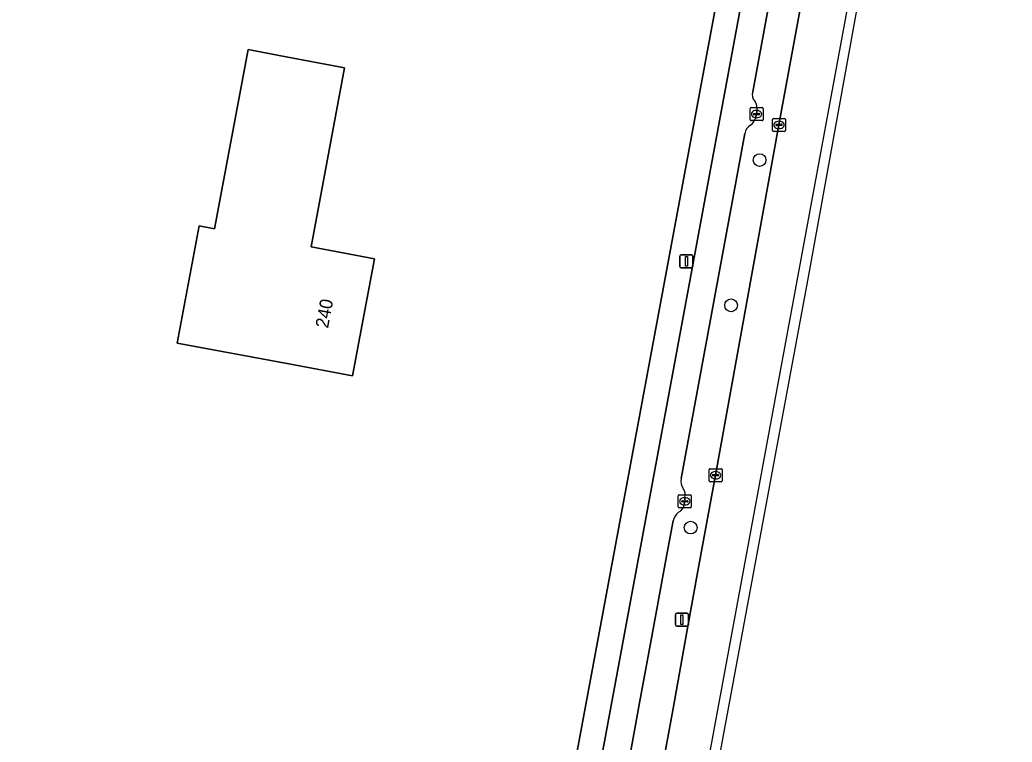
# Model space of a CAD drawing. Extents: x 161258 to 161838, y 380833 to 381727.
# Drawn here: x 161697.6 to 161774.1, y 381168.8 to 381224.5 of the extents above; entities that cross this region are included whole.
import ezdxf

# ---------------------------------------------------------------- set-up
doc = ezdxf.new("R2010")
doc.units = 0
for name, color, linetype in [('IMGEO_Berm_groen', 7, 'Continuous'), ('IMGEO_Boom', 7, 'Continuous'), ('IMGEO_Erf', 7, 'Continuous'), ('IMGEO_Fietspad_open', 7, 'Continuous'), ('IMGEO_Kolk', 7, 'Continuous'), ('IMGEO_Lichtmast', 7, 'Continuous'), ('IMGEO_OVBaan_gesloten', 7, 'Continuous'), ('IMGEO_Pand', 7, 'Continuous'), ('IMGEO_Pand_nummerreeks', 7, 'Continuous'), ('IMGEO_Rijbaan_regionaal_gesloten', 7, 'Continuous'), ('IMGEO_Voetpad_open', 7, 'Continuous')]:
    doc.layers.add(name, color=color, linetype=linetype)

msp = doc.modelspace()

# ---------------------------------------------------------------- linework, layer by layer
at = {"layer": 'IMGEO_Berm_groen'}
for points in [[(161749.906, 381182.432), (161751.199, 381189.4), (161756.087, 381216.391), (161759.764, 381236.501), (161759.812, 381236.731), (161757.806, 381237.074)], [(161756.973, 381234.746), (161754.062, 381218.948)], [(161754.387, 381217.443), (161754.355, 381217.217), (161754.307, 381217.001)], [(161753.462, 381215.738), (161748.553, 381189.132)], [(161748.843, 381187.633), (161748.825, 381187.388), (161748.776, 381187.177)], [(161747.932, 381185.874), (161747.38, 381182.889), (161746.436, 381177.828), (161745.35, 381171.862), (161744.465, 381167.019), (161743.243, 381160.292)], [(161738.935, 381137.075), (161736.688, 381124.974), (161739.276, 381124.46), (161741.999, 381139.338), (161745.882, 381160.426), (161747.045, 381166.542), (161747.93, 381171.425), (161748.988, 381177.338), (161749.906, 381182.432)]]:
    msp.add_lwpolyline(points, dxfattribs=at)
for centre, radius, start, end in [((161754.846, 381218.728), 0.814, 164.34392, 219.20512), ((161753.481, 381217.645), 0.929, 347.40505, 37.74697), ((161753.289, 381217.212), 1.04, 305.73201, 348.27754), ((161754.335, 381215.601), 0.884, 119.78436, 171.09059), ((161749.527, 381188.92), 0.996, 167.72981, 213.94161), ((161747.981, 381187.844), 0.887, 346.24075, 35.89637), ((161748.064, 381187.196), 0.713, 293.08221, 358.50607), ((161749.008, 381185.67), 1.095, 127.38602, 169.25509)]:
    msp.add_arc(centre, radius, start, end, dxfattribs=at)
at = {"layer": 'IMGEO_Boom'}
for centre in [(161754.592, 381213.675), (161752.398, 381202.487), (161749.281, 381185.361)]:
    msp.add_circle(centre, 0.489, dxfattribs=at)
at = {"layer": 'IMGEO_Erf'}
msp.add_lwpolyline([(161668.77, 381167.385), (161673.77, 381165.793), (161737.053, 381153.773), (161737.441, 381153.699), (161737.997, 381153.598), (161738.112, 381154.157), (161737.938, 381154.198), (161753.579, 381238.309), (161753.673, 381238.82), (161753.349, 381239.081), (161753.133, 381238.804), (161751.742, 381240.033), (161751.586, 381239.216), (161750.481, 381239.459), (161750.713, 381240.543), (161751.212, 381243.492), (161751.454, 381244.596), (161752.571, 381244.423), (161752.507, 381243.755), (161754.157, 381244.071), (161754.273, 381243.898), (161754.635, 381244.025), (161769.385, 381323.827)], dxfattribs=at)
msp.add_lwpolyline([(161715.169, 381222.186), (161717.694, 381221.709), (161722.609, 381220.792), (161720.033, 381206.986), (161724.904, 381206.076), (161723.22, 381197.055), (161718.305, 381197.972), (161709.716, 381199.575), (161711.402, 381208.608), (161712.591, 381208.386)], close=True, dxfattribs=at)
at = {"layer": 'IMGEO_Fietspad_open'}
for points in [[(161766.182, 381284.389), (161766.274, 381284.919), (161766.944, 381288.761), (161768.496, 381297.63), (161770.018, 381305.316), (161770.601, 381308.32), (161771.852, 381315.075), (161772.289, 381317.394), (161770.217, 381317.745), (161769.724, 381315.032), (161762.12, 381274.018), (161757.67, 381250), (161756.52, 381243.79), (161755.513, 381238.354), (161742.385, 381167.493), (161739.245, 381150.478), (161741.31, 381150.032), (161742.611, 381157.056), (161742.773, 381157.406), (161743.019, 381157.715)], [(161754.062, 381218.948), (161756.973, 381234.746)], [(161754.307, 381217.001), (161754.355, 381217.217), (161754.387, 381217.443)], [(161748.553, 381189.132), (161753.462, 381215.738)], [(161748.776, 381187.177), (161748.825, 381187.388), (161748.843, 381187.633)], [(161743.243, 381160.292), (161744.465, 381167.019), (161745.35, 381171.862), (161746.436, 381177.828), (161747.38, 381182.889), (161747.932, 381185.874)]]:
    msp.add_lwpolyline(points, dxfattribs=at)
for centre, radius, start, end in [((161754.846, 381218.728), 0.814, 164.34392, 219.20512), ((161753.481, 381217.645), 0.929, 347.40505, 37.74697), ((161753.289, 381217.212), 1.04, 305.73201, 348.27754), ((161754.335, 381215.601), 0.884, 119.78436, 171.09059), ((161749.527, 381188.92), 0.996, 167.72981, 213.94161), ((161747.981, 381187.844), 0.887, 346.24075, 35.89637), ((161748.064, 381187.196), 0.713, 293.08221, 358.50607), ((161749.008, 381185.67), 1.095, 127.38602, 169.25509)]:
    msp.add_arc(centre, radius, start, end, dxfattribs=at)
at = {"layer": 'IMGEO_Kolk'}
for p, q in [((161753.859, 381216.791), (161753.859, 381217.643)), ((161753.934, 381217.717), (161754.786, 381217.717)), ((161754.86, 381217.643), (161754.86, 381216.791)), ((161754.118, 381217.211), (161754.118, 381217.223)), ((161754.556, 381217.174), (161754.158, 381217.174)), ((161754.161, 381217.26), (161754.559, 381217.26)), ((161754.37, 381216.937), (161754.345, 381216.937)), ((161754.347, 381217.497), (161754.372, 381217.497)), ((161754.602, 381217.223), (161754.602, 381217.211)), ((161755.589, 381215.965), (161755.589, 381216.817)), ((161755.664, 381216.891), (161756.516, 381216.891)), ((161756.59, 381216.817), (161756.59, 381215.965)), ((161754.786, 381216.717), (161753.934, 381216.717)), ((161755.848, 381216.385), (161755.848, 381216.397)), ((161756.286, 381216.348), (161755.888, 381216.348)), ((161755.891, 381216.434), (161756.289, 381216.434)), ((161756.1, 381216.111), (161756.075, 381216.111)), ((161756.077, 381216.671), (161756.102, 381216.671)), ((161756.332, 381216.397), (161756.332, 381216.385)), ((161756.516, 381215.891), (161755.664, 381215.891)), ((161750.7, 381188.974), (161750.7, 381189.826)), ((161750.775, 381189.9), (161751.627, 381189.9)), ((161750.959, 381189.394), (161750.959, 381189.406)), ((161751.397, 381189.357), (161750.999, 381189.357)), ((161751.002, 381189.443), (161751.4, 381189.443)), ((161751.188, 381189.68), (161751.213, 381189.68)), ((161751.443, 381189.406), (161751.443, 381189.394)), ((161751.701, 381189.826), (161751.701, 381188.974)), ((161751.627, 381188.9), (161750.775, 381188.9)), ((161751.211, 381189.12), (161751.186, 381189.12)), ((161748.329, 381186.962), (161748.329, 381187.814)), ((161748.404, 381187.888), (161749.256, 381187.888)), ((161749.33, 381187.814), (161749.33, 381186.962)), ((161748.588, 381187.382), (161748.588, 381187.394)), ((161749.026, 381187.345), (161748.628, 381187.345)), ((161748.631, 381187.431), (161749.029, 381187.431)), ((161748.84, 381187.108), (161748.815, 381187.108)), ((161748.817, 381187.668), (161748.842, 381187.668)), ((161749.072, 381187.394), (161749.072, 381187.382)), ((161749.256, 381186.888), (161748.404, 381186.888))]:
    msp.add_line(p, q, dxfattribs=at)
for points in [[(161753.859, 381216.791), (161753.859, 381217.643)], [(161753.934, 381217.717), (161754.786, 381217.717)], [(161754.86, 381217.643), (161754.86, 381216.791)], [(161755.589, 381215.965), (161755.589, 381216.817)], [(161755.664, 381216.891), (161756.516, 381216.891)], [(161756.59, 381216.817), (161756.59, 381215.965)], [(161754.786, 381216.717), (161753.934, 381216.717)], [(161756.516, 381215.891), (161755.664, 381215.891)], [(161750.7, 381188.974), (161750.7, 381189.826)], [(161750.775, 381189.9), (161751.627, 381189.9)], [(161751.701, 381189.826), (161751.701, 381188.974)], [(161751.627, 381188.9), (161750.775, 381188.9)], [(161748.329, 381186.962), (161748.329, 381187.814)], [(161748.404, 381187.888), (161749.256, 381187.888)], [(161749.33, 381187.814), (161749.33, 381186.962)], [(161749.256, 381186.888), (161748.404, 381186.888)]]:
    msp.add_lwpolyline(points, dxfattribs=at)
for centre, radius, start, end in [((161753.936, 381217.641), 0.0765, 91.55205, 178.44795), ((161753.936, 381217.641), 0.0765, 91.55205, 178.44795), ((161754.784, 381217.641), 0.0765, 1.55205, 88.44795), ((161754.784, 381217.641), 0.0765, 1.55205, 88.44795), ((161754.158, 381217.22), 0.0403, 85.87752, 175.75265), ((161754.155, 381217.21), 0.0366, 178.93798, 274.71019), ((161754.559, 381217.217), 0.043, 264.86636, 352.45326), ((161754.563, 381217.222), 0.0386, 1.73085, 96.63898), ((161755.666, 381216.815), 0.0765, 91.55205, 178.44795), ((161755.666, 381216.815), 0.0765, 91.55205, 178.44795), ((161756.514, 381216.815), 0.0765, 1.55205, 88.44795), ((161756.514, 381216.815), 0.0765, 1.55205, 88.44795), ((161753.936, 381216.793), 0.0765, 181.55205, 268.44795), ((161753.936, 381216.793), 0.0765, 181.55205, 268.44795), ((161754.784, 381216.793), 0.0765, 271.55205, 358.44795), ((161754.784, 381216.793), 0.0765, 271.55205, 358.44795), ((161755.888, 381216.394), 0.0403, 85.87752, 175.75265), ((161755.885, 381216.384), 0.0366, 178.93798, 274.71019), ((161756.289, 381216.391), 0.043, 264.86636, 352.45326), ((161756.293, 381216.396), 0.0386, 1.73085, 96.63898), ((161755.666, 381215.967), 0.0765, 181.55205, 268.44795), ((161755.666, 381215.967), 0.0765, 181.55205, 268.44795), ((161756.514, 381215.967), 0.0765, 271.55205, 358.44795), ((161756.514, 381215.967), 0.0765, 271.55205, 358.44795), ((161750.777, 381189.824), 0.0765, 91.55205, 178.44795), ((161750.777, 381189.824), 0.0765, 91.55205, 178.44795), ((161750.999, 381189.403), 0.0403, 85.87752, 175.75265), ((161750.996, 381189.393), 0.0366, 178.93798, 274.71019), ((161751.4, 381189.4), 0.043, 264.86636, 352.45326), ((161751.404, 381189.405), 0.0386, 1.73085, 96.63898), ((161751.625, 381189.824), 0.0765, 1.55205, 88.44795), ((161751.625, 381189.824), 0.0765, 1.55205, 88.44795), ((161750.777, 381188.976), 0.0765, 181.55205, 268.44795), ((161750.777, 381188.976), 0.0765, 181.55205, 268.44795), ((161751.625, 381188.976), 0.0765, 271.55205, 358.44795), ((161751.625, 381188.976), 0.0765, 271.55205, 358.44795), ((161748.406, 381187.812), 0.0765, 91.55205, 178.44795), ((161748.406, 381187.812), 0.0765, 91.55205, 178.44795), ((161749.254, 381187.812), 0.0765, 1.55205, 88.44795), ((161749.254, 381187.812), 0.0765, 1.55205, 88.44795), ((161748.628, 381187.391), 0.0403, 85.87752, 175.75265), ((161748.625, 381187.381), 0.0366, 178.93798, 274.71019), ((161749.029, 381187.388), 0.043, 264.86636, 352.45326), ((161749.033, 381187.393), 0.0386, 1.73085, 96.63898), ((161748.406, 381186.964), 0.0765, 181.55205, 268.44795), ((161748.406, 381186.964), 0.0765, 181.55205, 268.44795), ((161749.254, 381186.964), 0.0765, 271.55205, 358.44795), ((161749.254, 381186.964), 0.0765, 271.55205, 358.44795)]:
    msp.add_arc(centre, radius, start, end, dxfattribs=at)
for centre, major_axis, ratio, start_param, end_param in [((161754.346, 381217.217), (-0.387, 0.002), 0.722429, 4.712389, 7.853982), ((161754.371, 381217.217), (-0.39, 0.002), 0.717154, 1.570796, 4.712389), ((161756.076, 381216.391), (-0.387, 0.002), 0.722429, 4.712389, 7.853982), ((161756.101, 381216.391), (-0.39, 0.002), 0.717154, 1.570796, 4.712389), ((161751.187, 381189.4), (-0.387, 0.002), 0.722429, 4.712389, 7.853982), ((161751.212, 381189.4), (-0.39, 0.002), 0.717154, 1.570796, 4.712389), ((161748.816, 381187.388), (-0.387, 0.002), 0.722429, 4.712389, 7.853982), ((161748.841, 381187.388), (-0.39, 0.002), 0.717154, 1.570796, 4.712389)]:
    msp.add_ellipse(centre, major_axis=major_axis, ratio=ratio, start_param=start_param, end_param=end_param, dxfattribs=at)
at = {"layer": 'IMGEO_Lichtmast'}
for p, q in [((161748.455, 381205.469), (161748.455, 381206.269)), ((161748.455, 381206.269), (161748.455, 381205.469)), ((161748.555, 381206.369), (161749.345, 381206.369)), ((161749.345, 381206.369), (161748.555, 381206.369)), ((161749.445, 381206.269), (161749.445, 381205.469)), ((161749.445, 381205.469), (161749.445, 381206.269)), ((161749.345, 381205.369), (161748.555, 381205.369)), ((161748.555, 381205.369), (161749.345, 381205.369)), ((161748.113, 381177.864), (161748.113, 381178.664)), ((161748.113, 381178.664), (161748.113, 381177.864)), ((161748.213, 381178.764), (161749.003, 381178.764)), ((161749.003, 381178.764), (161748.213, 381178.764)), ((161749.103, 381178.664), (161749.103, 381177.864)), ((161749.103, 381177.864), (161749.103, 381178.664)), ((161749.003, 381177.764), (161748.213, 381177.764)), ((161748.213, 381177.764), (161749.003, 381177.764))]:
    msp.add_line(p, q, dxfattribs=at)
for points in [[(161748.875, 381206.244), (161749.025, 381206.244), (161749.025, 381205.494), (161748.875, 381205.494), (161748.875, 381206.244)], [(161748.533, 381178.639), (161748.683, 381178.639), (161748.683, 381177.889), (161748.533, 381177.889), (161748.533, 381178.639)]]:
    msp.add_lwpolyline(points, dxfattribs=at)
for centre, start, end in [((161748.555, 381206.269), 90, 180), ((161748.555, 381206.269), 90, 180), ((161749.345, 381206.269), 0, 90), ((161749.345, 381206.269), 360, 90), ((161748.555, 381205.469), 180, 270), ((161748.555, 381205.469), 180, 270), ((161749.345, 381205.469), 270, 0), ((161749.345, 381205.469), 270, 0), ((161748.213, 381178.664), 90, 180), ((161748.213, 381178.664), 90, 180), ((161749.003, 381178.664), 0, 90), ((161749.003, 381178.664), 360, 90), ((161748.213, 381177.864), 180, 270), ((161748.213, 381177.864), 180, 270), ((161749.003, 381177.864), 270, 0), ((161749.003, 381177.864), 270, 0)]:
    msp.add_arc(centre, 0.1, start, end, dxfattribs=at)
at = {"layer": 'IMGEO_OVBaan_gesloten'}
msp.add_lwpolyline([(161733.581, 381071.116), (161732.705, 381071.238), (161742.349, 381122.541), (161776.386, 381306.634), (161776.704, 381306.578), (161771.577, 381277.677), (161758.366, 381204.804), (161740.263, 381107.16), (161733.581, 381071.116)], dxfattribs=at)
at = {"layer": 'IMGEO_Pand'}
msp.add_lwpolyline([(161718.305, 381197.972), (161723.22, 381197.055), (161724.904, 381206.076), (161720.033, 381206.986), (161722.609, 381220.792), (161717.694, 381221.709), (161715.169, 381222.186), (161712.591, 381208.386), (161711.402, 381208.608), (161709.716, 381199.575)], close=True, dxfattribs=at)
at = {"layer": 'IMGEO_Rijbaan_regionaal_gesloten'}
for points in [[(161732.705, 381071.484), (161732.705, 381071.238), (161742.349, 381122.541), (161776.386, 381306.634), (161779.513, 381323.547), (161779.709, 381323.516), (161781.032, 381330.976), (161790.829, 381386.201), (161813.475, 381504.752), (161831.216, 381599.902), (161831.886, 381604.233), (161835.772, 381629.362), (161830.258, 381630.974)], [(161759.764, 381236.501), (161756.087, 381216.391), (161751.199, 381189.4), (161749.906, 381182.432), (161748.988, 381177.338), (161747.93, 381171.425), (161747.045, 381166.542), (161745.882, 381160.426), (161741.999, 381139.338), (161739.276, 381124.46), (161738.181, 381118.466), (161737.928, 381117.198), (161736.994, 381112.113), (161736.408, 381108.929), (161735.457, 381103.754), (161734.053, 381096.116), (161732.968, 381090.212), (161732.671, 381088.606)]]:
    msp.add_lwpolyline(points, dxfattribs=at)
at = {"layer": 'IMGEO_Voetpad_open'}
for points in [[(161770.217, 381317.745), (161771.375, 381324.109), (161769.385, 381323.827), (161754.635, 381244.025), (161753.673, 381238.82), (161753.579, 381238.309), (161737.938, 381154.198), (161738.112, 381154.157), (161737.997, 381153.598), (161737.441, 381153.699), (161737.053, 381153.773), (161736.521, 381150.931), (161736.147, 381148.935), (161736.914, 381148.802)], [(161739.245, 381150.478), (161742.385, 381167.493), (161755.513, 381238.354), (161756.52, 381243.79), (161757.67, 381250), (161762.12, 381274.018), (161769.724, 381315.032), (161770.217, 381317.745)]]:
    msp.add_lwpolyline(points, dxfattribs=at)

# ---------------------------------------------------------------- texts
at = {"layer": 'IMGEO_Pand_nummerreeks'}
msp.add_text('240', height=1, rotation=79.42599, dxfattribs=at).set_placement((161721.332, 381200.677))

doc.saveas('drawing.dxf')
